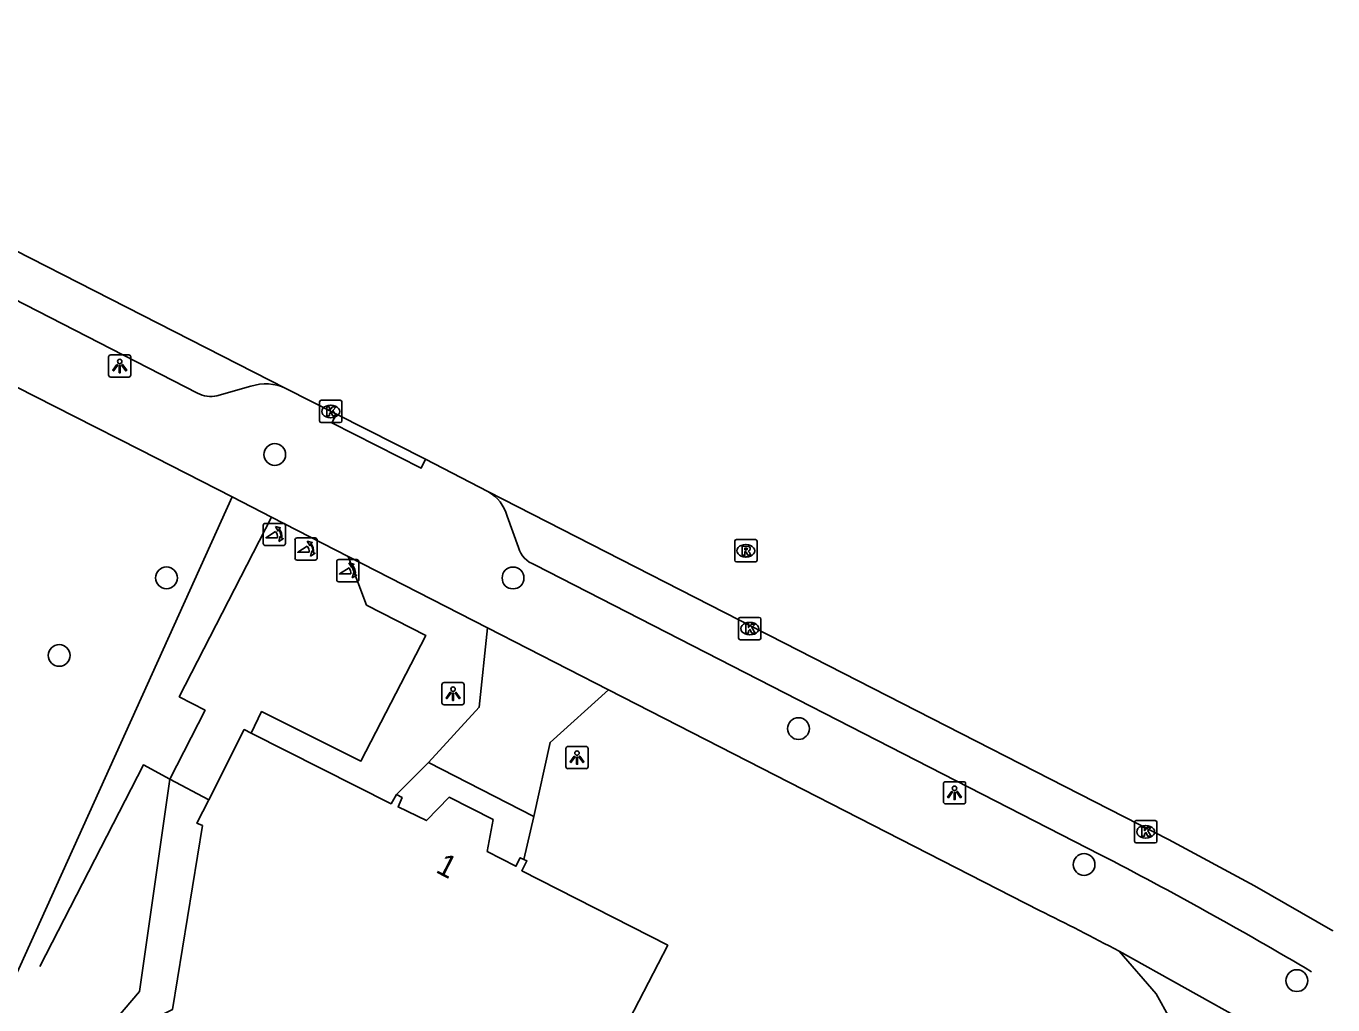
# Model space of a CAD drawing. Extents: x 159503 to 160347, y 382525 to 383272.
# Drawn here: x 160288.6 to 160347.2, y 382897.3 to 382941.2 of the extents above; entities that cross this region are included whole.
import ezdxf

# ---------------------------------------------------------------- set-up
doc = ezdxf.new("R2010")
doc.units = 0
for name, color, linetype in [('IMGEO_Boom', 7, 'Continuous'), ('IMGEO_Groenvoorziening', 7, 'Continuous'), ('IMGEO_Hek', 7, 'Continuous'), ('IMGEO_Kolk', 7, 'Continuous'), ('IMGEO_Lichtpunt', 7, 'Continuous'), ('IMGEO_Loofbos', 7, 'Continuous'), ('IMGEO_Pand', 7, 'Continuous'), ('IMGEO_Pand_nummerreeks', 7, 'Continuous'), ('IMGEO_Parkeervlak_open', 7, 'Continuous'), ('IMGEO_Poller', 7, 'Continuous'), ('IMGEO_Rijbaan_lokaal_open', 7, 'Continuous'), ('IMGEO_Rioolput', 7, 'Continuous'), ('IMGEO_Voetpad_open', 7, 'Continuous')]:
    doc.layers.add(name, color=color, linetype=linetype)

msp = doc.modelspace()

# ---------------------------------------------------------------- linework, layer by layer
at = {"layer": 'IMGEO_Boom'}
for centre in [(160299.715, 382921.985), (160294.859, 382916.452), (160310.401, 382916.448), (160290.047, 382912.974), (160323.206, 382909.691), (160336.012, 382903.594), (160345.555, 382898.387)]:
    msp.add_circle(centre, 0.489, dxfattribs=at)
at = {"layer": 'IMGEO_Groenvoorziening'}
msp.add_lwpolyline([(160337.58, 382899.708), (160339.246, 382897.788), (160339.864, 382896.69), (160340.213, 382895.657), (160340.37, 382894.676), (160340.378, 382893.79), (160340.246, 382892.846), (160340.012, 382892.038), (160339.449, 382890.88), (160338.678, 382889.878), (160313.605, 382875.081)], dxfattribs=at)
at = {"layer": 'IMGEO_Hek'}
for points in [[(160289.183, 382899.021), (160293.821, 382908.06), (160295.01, 382907.43)], [(160295.01, 382907.43), (160296.757, 382906.504)]]:
    msp.add_lwpolyline(points, dxfattribs=at)
at = {"layer": 'IMGEO_Kolk'}
for p, q in [((160301.725, 382923.492), (160301.725, 382924.344)), ((160301.8, 382924.418), (160302.652, 382924.418)), ((160302.213, 382924.198), (160302.238, 382924.198)), ((160302.726, 382924.344), (160302.726, 382923.492)), ((160302.652, 382923.418), (160301.8, 382923.418)), ((160302.236, 382923.638), (160302.211, 382923.638)), ((160320.593, 382914.677), (160321.445, 382914.677)), ((160320.518, 382913.751), (160320.518, 382914.603)), ((160321.006, 382914.457), (160321.031, 382914.457)), ((160321.519, 382914.603), (160321.519, 382913.751)), ((160321.445, 382913.677), (160320.593, 382913.677)), ((160321.029, 382913.897), (160321.004, 382913.897)), ((160338.275, 382904.638), (160338.275, 382905.49)), ((160338.35, 382905.564), (160339.202, 382905.564)), ((160338.763, 382905.344), (160338.788, 382905.344)), ((160339.276, 382905.49), (160339.276, 382904.638)), ((160338.786, 382904.784), (160338.761, 382904.784)), ((160339.202, 382904.564), (160338.35, 382904.564))]:
    msp.add_line(p, q, dxfattribs=at)
for points in [[(160301.725, 382923.492), (160301.725, 382924.344)], [(160301.8, 382924.418), (160302.652, 382924.418)], [(160302.046, 382924.118), (160302.169, 382924.118), (160302.169, 382923.967), (160302.299, 382924.118), (160302.463, 382924.118), (160302.317, 382923.967), (160302.47, 382923.718), (160302.318, 382923.718), (160302.233, 382923.882), (160302.169, 382923.815), (160302.169, 382923.718), (160302.046, 382923.718), (160302.046, 382924.118)], [(160302.726, 382924.344), (160302.726, 382923.492)], [(160302.652, 382923.418), (160301.8, 382923.418)], [(160320.593, 382914.677), (160321.445, 382914.677)], [(160320.518, 382913.751), (160320.518, 382914.603)], [(160320.839, 382914.377), (160320.962, 382914.377), (160320.962, 382914.226), (160321.092, 382914.377), (160321.256, 382914.377), (160321.11, 382914.226), (160321.263, 382913.977), (160321.111, 382913.977), (160321.026, 382914.141), (160320.962, 382914.074), (160320.962, 382913.977), (160320.839, 382913.977), (160320.839, 382914.377)], [(160321.519, 382914.603), (160321.519, 382913.751)], [(160321.445, 382913.677), (160320.593, 382913.677)], [(160338.275, 382904.638), (160338.275, 382905.49)], [(160338.35, 382905.564), (160339.202, 382905.564)], [(160338.596, 382905.264), (160338.719, 382905.264), (160338.719, 382905.113), (160338.849, 382905.264), (160339.013, 382905.264), (160338.867, 382905.113), (160339.02, 382904.864), (160338.868, 382904.864), (160338.783, 382905.028), (160338.719, 382904.961), (160338.719, 382904.864), (160338.596, 382904.864), (160338.596, 382905.264)], [(160339.276, 382905.49), (160339.276, 382904.638)], [(160339.202, 382904.564), (160338.35, 382904.564)]]:
    msp.add_lwpolyline(points, dxfattribs=at)
for centre, start, end in [((160301.802, 382924.342), 91.55205, 178.44795), ((160301.802, 382924.342), 91.55205, 178.44795), ((160302.65, 382924.342), 1.55205, 88.44795), ((160302.65, 382924.342), 1.55205, 88.44795), ((160301.802, 382923.494), 181.55205, 268.44795), ((160301.802, 382923.494), 181.55205, 268.44795), ((160302.65, 382923.494), 271.55205, 358.44795), ((160302.65, 382923.494), 271.55205, 358.44795), ((160320.595, 382914.601), 91.55205, 178.44795), ((160320.595, 382914.601), 91.55205, 178.44795), ((160321.443, 382914.601), 1.55205, 88.44795), ((160321.443, 382914.601), 1.55205, 88.44795), ((160320.595, 382913.753), 181.55205, 268.44795), ((160320.595, 382913.753), 181.55205, 268.44795), ((160321.443, 382913.753), 271.55205, 358.44795), ((160321.443, 382913.753), 271.55205, 358.44795), ((160338.352, 382905.488), 91.55205, 178.44795), ((160338.352, 382905.488), 91.55205, 178.44795), ((160339.2, 382905.488), 1.55205, 88.44795), ((160339.2, 382905.488), 1.55205, 88.44795), ((160338.352, 382904.64), 181.55205, 268.44795), ((160338.352, 382904.64), 181.55205, 268.44795), ((160339.2, 382904.64), 271.55205, 358.44795), ((160339.2, 382904.64), 271.55205, 358.44795)]:
    msp.add_arc(centre, 0.0765, start, end, dxfattribs=at)
for centre, major_axis, ratio, start_param, end_param in [((160302.212, 382923.918), (-0.387, 0.002), 0.722429, 4.712389, 7.853982), ((160302.237, 382923.918), (-0.39, 0.002), 0.717154, 1.570796, 4.712389), ((160321.005, 382914.177), (-0.387, 0.002), 0.722429, 4.712389, 7.853982), ((160321.03, 382914.177), (-0.39, 0.002), 0.717154, 1.570796, 4.712389), ((160338.762, 382905.064), (-0.387, 0.002), 0.722429, 4.712389, 7.853982), ((160338.787, 382905.064), (-0.39, 0.002), 0.717154, 1.570796, 4.712389)]:
    msp.add_ellipse(centre, major_axis=major_axis, ratio=ratio, start_param=start_param, end_param=end_param, dxfattribs=at)
at = {"layer": 'IMGEO_Lichtpunt'}
for p, q in [((160292.262, 382926.362), (160292.262, 382925.555)), ((160292.262, 382926.362), (160292.262, 382925.555)), ((160293.164, 382926.457), (160292.356, 382926.457)), ((160293.164, 382926.457), (160292.356, 382926.457)), ((160293.258, 382925.555), (160293.258, 382926.362)), ((160293.258, 382925.555), (160293.258, 382926.362)), ((160292.356, 382925.461), (160293.164, 382925.461)), ((160292.356, 382925.461), (160293.164, 382925.461)), ((160308.115, 382911.757), (160307.307, 382911.757)), ((160308.115, 382911.757), (160307.307, 382911.757)), ((160307.213, 382911.662), (160307.213, 382910.855)), ((160307.213, 382911.662), (160307.213, 382910.855)), ((160308.209, 382910.855), (160308.209, 382911.662)), ((160308.209, 382910.855), (160308.209, 382911.662)), ((160307.307, 382910.761), (160308.115, 382910.761)), ((160307.307, 382910.761), (160308.115, 382910.761)), ((160312.772, 382908.796), (160312.772, 382907.989)), ((160312.772, 382908.796), (160312.772, 382907.989)), ((160313.674, 382908.891), (160312.866, 382908.891)), ((160313.674, 382908.891), (160312.866, 382908.891)), ((160313.768, 382907.989), (160313.768, 382908.796)), ((160313.768, 382907.989), (160313.768, 382908.796)), ((160312.866, 382907.895), (160313.674, 382907.895)), ((160312.866, 382907.895), (160313.674, 382907.895)), ((160329.703, 382907.216), (160329.703, 382906.409)), ((160329.703, 382907.216), (160329.703, 382906.409)), ((160330.605, 382907.311), (160329.797, 382907.311)), ((160330.605, 382907.311), (160329.797, 382907.311)), ((160330.699, 382906.409), (160330.699, 382907.216)), ((160330.699, 382906.409), (160330.699, 382907.216)), ((160329.797, 382906.315), (160330.605, 382906.315)), ((160329.797, 382906.315), (160330.605, 382906.315))]:
    msp.add_line(p, q, dxfattribs=at)
for points in [[(160292.636, 382926.026), (160292.675, 382925.998), (160292.487, 382925.736), (160292.449, 382925.763), (160292.636, 382926.026)], [(160292.738, 382925.978), (160292.785, 382925.978), (160292.785, 382925.656), (160292.738, 382925.656), (160292.738, 382925.978)], [(160292.848, 382925.998), (160292.886, 382926.025), (160293.073, 382925.763), (160293.034, 382925.735), (160292.848, 382925.998)], [(160307.587, 382911.326), (160307.626, 382911.298), (160307.438, 382911.036), (160307.4, 382911.063), (160307.587, 382911.326)], [(160307.689, 382911.278), (160307.736, 382911.278), (160307.736, 382910.956), (160307.689, 382910.956), (160307.689, 382911.278)], [(160307.799, 382911.298), (160307.837, 382911.325), (160308.024, 382911.063), (160307.985, 382911.035), (160307.799, 382911.298)], [(160313.146, 382908.46), (160313.185, 382908.432), (160312.997, 382908.17), (160312.959, 382908.197), (160313.146, 382908.46)], [(160313.248, 382908.412), (160313.295, 382908.412), (160313.295, 382908.09), (160313.248, 382908.09), (160313.248, 382908.412)], [(160313.358, 382908.432), (160313.396, 382908.459), (160313.583, 382908.197), (160313.544, 382908.169), (160313.358, 382908.432)], [(160330.077, 382906.88), (160330.116, 382906.852), (160329.928, 382906.59), (160329.89, 382906.617), (160330.077, 382906.88)], [(160330.179, 382906.832), (160330.226, 382906.832), (160330.226, 382906.51), (160330.179, 382906.51), (160330.179, 382906.832)], [(160330.289, 382906.852), (160330.327, 382906.879), (160330.514, 382906.617), (160330.475, 382906.589), (160330.289, 382906.852)]]:
    msp.add_lwpolyline(points, dxfattribs=at)
for centre in [(160292.761, 382926.16), (160307.712, 382911.46), (160313.271, 382908.594), (160330.202, 382907.014)]:
    msp.add_circle(centre, 0.0994, dxfattribs=at)
for centre, start, end in [((160292.356, 382926.362), 90, 180), ((160292.356, 382926.362), 90, 180), ((160293.164, 382926.362), 0, 90), ((160293.164, 382926.362), 0, 90), ((160292.356, 382925.555), 180, 270), ((160292.356, 382925.555), 180, 270), ((160293.164, 382925.555), 270, 0), ((160293.164, 382925.555), 270, 360), ((160307.307, 382911.662), 90, 180), ((160307.307, 382911.662), 90, 180), ((160308.115, 382911.662), 0, 90), ((160308.115, 382911.662), 0, 90), ((160307.307, 382910.855), 180, 270), ((160307.307, 382910.855), 180, 270), ((160308.115, 382910.855), 270, 0), ((160308.115, 382910.855), 270, 360), ((160312.866, 382908.796), 90, 180), ((160312.866, 382908.796), 90, 180), ((160313.674, 382908.796), 0, 90), ((160313.674, 382908.796), 0, 90), ((160312.866, 382907.989), 180, 270), ((160312.866, 382907.989), 180, 270), ((160313.674, 382907.989), 270, 0), ((160313.674, 382907.989), 270, 360), ((160329.797, 382907.216), 90, 180), ((160329.797, 382907.216), 90, 180), ((160330.605, 382907.216), 0, 90), ((160330.605, 382907.216), 0, 90), ((160329.797, 382906.409), 180, 270), ((160329.797, 382906.409), 180, 270), ((160330.605, 382906.409), 270, 0), ((160330.605, 382906.409), 270, 360)]:
    msp.add_arc(centre, 0.0946, start, end, dxfattribs=at)
at = {"layer": 'IMGEO_Loofbos'}
msp.add_lwpolyline([(160297.798, 382920.081), (160281.12, 382883.208)], dxfattribs=at)
at = {"layer": 'IMGEO_Pand'}
for points in [[(160296.757, 382906.504), (160298.346, 382909.65), (160298.653, 382909.494)], [(160305.168, 382906.741), (160304.929, 382906.318), (160298.653, 382909.494)], [(160296.757, 382906.504), (160296.224, 382905.449), (160296.47, 382905.339), (160295.13, 382897.097), (160294.615, 382896.84), (160292.189, 382894.395), (160290.933, 382888.185)], [(160305.168, 382906.741), (160305.426, 382906.598), (160305.244, 382906.18), (160306.516, 382905.568), (160307.54, 382906.616), (160309.508, 382905.61), (160309.243, 382904.181), (160310.534, 382903.517), (160310.728, 382903.898), (160310.892, 382903.819)], [(160310.892, 382903.819), (160311.025, 382903.755), (160310.795, 382903.318), (160317.343, 382899.976), (160315.181, 382895.795), (160314.983, 382895.908), (160308.995, 382890.048), (160309.03, 382889.941), (160309.117, 382889.708), (160309.132, 382889.471), (160308.622, 382886.049), (160308.57, 382885.927), (160308.415, 382885.684), (160307.904, 382885.173)]]:
    msp.add_lwpolyline(points, dxfattribs=at)
at = {"layer": 'IMGEO_Parkeervlak_open'}
for points in [[(160295.01, 382907.43), (160296.593, 382910.516), (160295.433, 382911.12), (160299.564, 382919.177)], [(160298.653, 382909.494), (160299.127, 382910.458), (160303.576, 382908.234), (160306.497, 382913.866), (160303.833, 382915.235), (160303.004, 382917.415)]]:
    msp.add_lwpolyline(points, dxfattribs=at)
at = {"layer": 'IMGEO_Poller'}
for p, q in [((160299.199, 382918.803), (160299.199, 382917.996)), ((160299.199, 382918.803), (160299.199, 382917.996)), ((160300.101, 382918.898), (160299.293, 382918.898)), ((160300.101, 382918.898), (160299.293, 382918.898)), ((160300.195, 382917.996), (160300.195, 382918.803)), ((160300.195, 382917.996), (160300.195, 382918.803)), ((160300.623, 382918.15), (160300.623, 382917.343)), ((160300.623, 382918.15), (160300.623, 382917.343)), ((160301.525, 382918.245), (160300.717, 382918.245)), ((160301.525, 382918.245), (160300.717, 382918.245)), ((160301.619, 382917.343), (160301.619, 382918.15)), ((160301.619, 382917.343), (160301.619, 382918.15)), ((160299.293, 382917.901), (160300.101, 382917.901)), ((160299.293, 382917.901), (160300.101, 382917.901)), ((160300.717, 382917.248), (160301.525, 382917.248)), ((160300.717, 382917.248), (160301.525, 382917.248)), ((160302.493, 382917.177), (160302.493, 382916.37)), ((160302.493, 382917.177), (160302.493, 382916.37)), ((160303.395, 382917.272), (160302.587, 382917.272)), ((160303.395, 382917.272), (160302.587, 382917.272)), ((160303.489, 382916.37), (160303.489, 382917.177)), ((160303.489, 382916.37), (160303.489, 382917.177)), ((160302.587, 382916.275), (160303.395, 382916.275)), ((160302.587, 382916.275), (160303.395, 382916.275))]:
    msp.add_line(p, q, dxfattribs=at)
for points in [[(160299.878, 382918.627), (160299.866, 382918.554), (160299.741, 382918.759)], [(160299.741, 382918.759), (160299.972, 382918.693), (160299.901, 382918.661)], [(160299.834, 382918.254), (160299.321, 382918.254), (160299.751, 382918.529)], [(160299.894, 382918.082), (160299.96, 382918.313), (160299.99, 382918.245)], [(160300.026, 382918.218), (160300.098, 382918.207), (160299.894, 382918.082)], [(160301.258, 382917.601), (160300.745, 382917.601), (160301.175, 382917.876)], [(160301.302, 382917.974), (160301.29, 382917.901), (160301.165, 382918.106)], [(160301.165, 382918.106), (160301.396, 382918.04), (160301.325, 382918.008)], [(160301.318, 382917.429), (160301.384, 382917.66), (160301.414, 382917.592)], [(160301.45, 382917.565), (160301.522, 382917.554), (160301.318, 382917.429)], [(160303.172, 382917.001), (160303.16, 382916.928), (160303.035, 382917.133)], [(160303.035, 382917.133), (160303.266, 382917.067), (160303.195, 382917.035)], [(160303.128, 382916.628), (160302.615, 382916.628), (160303.045, 382916.903)], [(160303.188, 382916.456), (160303.254, 382916.687), (160303.284, 382916.619)], [(160303.32, 382916.592), (160303.392, 382916.581), (160303.188, 382916.456)]]:
    msp.add_lwpolyline(points, dxfattribs=at)
for centre, radius, start, end in [((160299.293, 382918.803), 0.0946, 90, 180), ((160299.293, 382918.803), 0.0946, 90, 180), ((160300.101, 382918.803), 0.0946, 0, 90), ((160300.101, 382918.803), 0.0946, 0, 90), ((160299.506, 382918.304), 0.332, 351.32473, 42.4854), ((160299.52, 382918.314), 0.476, 351.75274, 41.16905), ((160299.52, 382918.314), 0.516, 349.35686, 42.29123), ((160300.717, 382918.15), 0.0946, 90, 180), ((160300.717, 382918.15), 0.0946, 90, 180), ((160301.525, 382918.15), 0.0946, 0, 90), ((160301.525, 382918.15), 0.0946, 0, 90), ((160299.293, 382917.996), 0.0946, 180, 270), ((160299.293, 382917.996), 0.0946, 180, 270), ((160300.101, 382917.996), 0.0946, 270, 0), ((160300.101, 382917.996), 0.0946, 270, 0), ((160300.93, 382917.651), 0.332, 351.32473, 42.4854), ((160300.944, 382917.661), 0.476, 351.75274, 41.16905), ((160300.944, 382917.661), 0.516, 349.35686, 42.29123), ((160300.717, 382917.343), 0.0946, 180, 270), ((160300.717, 382917.343), 0.0946, 180, 270), ((160301.525, 382917.343), 0.0946, 270, 0), ((160301.525, 382917.343), 0.0946, 270, 0), ((160302.587, 382917.177), 0.0946, 90, 180), ((160302.587, 382917.177), 0.0946, 90, 180), ((160302.814, 382916.688), 0.476, 351.75274, 41.16905), ((160302.814, 382916.688), 0.516, 349.35686, 42.29123), ((160303.395, 382917.177), 0.0946, 0, 90), ((160303.395, 382917.177), 0.0946, 0, 90), ((160302.8, 382916.678), 0.332, 351.32473, 42.4854), ((160302.587, 382916.37), 0.0946, 180, 270), ((160302.587, 382916.37), 0.0946, 180, 270), ((160303.395, 382916.37), 0.0946, 270, 0), ((160303.395, 382916.37), 0.0946, 270, 0)]:
    msp.add_arc(centre, radius, start, end, dxfattribs=at)
at = {"layer": 'IMGEO_Rijbaan_lokaal_open'}
for points in [[(160279.467, 382935.529), (160300.207, 382924.953)], [(160302.485, 382923.802), (160300.207, 382924.953)], [(160302.485, 382923.802), (160306.48, 382921.77)], [(160309.276, 382920.322), (160306.48, 382921.77)], [(160347.17, 382900.617), (160347.17, 382900.617), (160343.654, 382902.641), (160339.795, 382904.723), (160309.276, 382920.322)]]:
    msp.add_lwpolyline(points, dxfattribs=at)
at = {"layer": 'IMGEO_Rioolput'}
for p, q in [((160320.418, 382918.169), (160321.27, 382918.169)), ((160320.343, 382917.243), (160320.343, 382918.095)), ((160320.831, 382917.949), (160320.856, 382917.949)), ((160321.344, 382918.095), (160321.344, 382917.243)), ((160321.27, 382917.169), (160320.418, 382917.169)), ((160320.854, 382917.389), (160320.829, 382917.389))]:
    msp.add_line(p, q, dxfattribs=at)
for points in [[(160320.418, 382918.169), (160321.27, 382918.169)], [(160320.343, 382917.243), (160320.343, 382918.095)], [(160320.932, 382917.867), (160320.68, 382917.869), (160320.68, 382917.469)], [(160320.68, 382917.469), (160320.804, 382917.469), (160320.804, 382917.631), (160320.815, 382917.631)], [(160320.858, 382917.788), (160320.804, 382917.788), (160320.804, 382917.707)], [(160320.804, 382917.707), (160320.856, 382917.707)], [(160320.862, 382917.602), (160320.933, 382917.469), (160321.073, 382917.469), (160321.008, 382917.595)], [(160321.344, 382918.095), (160321.344, 382917.243)], [(160321.27, 382917.169), (160320.418, 382917.169)]]:
    msp.add_lwpolyline(points, dxfattribs=at)
for centre, radius, start, end in [((160320.42, 382918.093), 0.0765, 91.55205, 178.44795), ((160320.42, 382918.093), 0.0765, 91.55205, 178.44795), ((160321.268, 382918.093), 0.0765, 1.55205, 88.44795), ((160321.268, 382918.093), 0.0765, 1.55205, 88.44795), ((160320.814, 382917.578), 0.0533, 26.02933, 88.69889), ((160320.84, 382917.896), 0.19, 274.7715, 282.96867), ((160320.864, 382917.692), 0.0964, 77.00612, 93.18647), ((160320.878, 382917.749), 0.0378, 276.66336, 79.67722), ((160320.931, 382917.757), 0.109, 350.36119, 89.41601), ((160320.929, 382917.757), 0.112, 277.58423, 350.98172), ((160320.913, 382917.542), 0.108, 29.51342, 73.79051), ((160320.42, 382917.245), 0.0765, 181.55205, 268.44795), ((160320.42, 382917.245), 0.0765, 181.55205, 268.44795), ((160321.268, 382917.245), 0.0765, 271.55205, 358.44795), ((160321.268, 382917.245), 0.0765, 271.55205, 358.44795)]:
    msp.add_arc(centre, radius, start, end, dxfattribs=at)
for centre, major_axis, ratio, start_param, end_param in [((160320.83, 382917.669), (-0.387, 0.002), 0.722429, 4.712389, 7.853982), ((160320.855, 382917.669), (-0.39, 0.002), 0.717154, 1.570796, 4.712389)]:
    msp.add_ellipse(centre, major_axis=major_axis, ratio=ratio, start_param=start_param, end_param=end_param, dxfattribs=at)
at = {"layer": 'IMGEO_Voetpad_open'}
for points in [[(160256.305, 382941.201), (160267.269, 382935.624), (160290.738, 382923.687), (160293.682, 382922.189), (160297.798, 382920.081)], [(160296.253, 382924.736), (160278.588, 382933.799)], [(160298.643, 382925.046), (160297.124, 382924.622)], [(160306.48, 382921.77), (160306.274, 382921.37), (160302.268, 382923.408), (160302.485, 382923.802)], [(160297.798, 382920.081), (160299.564, 382919.177)], [(160299.564, 382919.177), (160303.004, 382917.415)], [(160310.142, 382919.223), (160310.641, 382917.818)], [(160303.004, 382917.415), (160309.263, 382914.21)], [(160311.385, 382917.044), (160336.75, 382904.037)], [(160309.263, 382914.21), (160308.889, 382910.65), (160306.616, 382908.178)], [(160309.263, 382914.21), (160314.69, 382911.431)], [(160314.69, 382911.431), (160312.062, 382909.07), (160311.33, 382905.751)], [(160314.69, 382911.431), (160334.009, 382901.537)], [(160306.616, 382908.178), (160305.168, 382906.741)], [(160311.33, 382905.751), (160306.616, 382908.178)], [(160302.807, 382880.492), (160303.398, 382879.562), (160299.29, 382878.733), (160291.637, 382882.353), (160289.455, 382886.708), (160290.802, 382894.566), (160293.646, 382897.904), (160295.01, 382907.43)], [(160295.01, 382907.43), (160296.757, 382906.504)], [(160311.33, 382905.751), (160310.892, 382903.819)], [(160337.58, 382899.708), (160343.472, 382896.422), (160344.077, 382896.065)]]:
    msp.add_lwpolyline(points, dxfattribs=at)
for centre, radius, start, end in [((160296.84, 382925.84), 1.25, 241.97465, 283.11192), ((160299.313, 382923.111), 2.048, 64.10606, 109.088), ((160308.368, 382918.716), 1.845, 15.96032, 60.51512), ((160311.721, 382918.111), 1.119, 195.19176, 252.54388), ((160252.702, 382741.444), 183.032, 59.27396, 62.6645), ((160263.814, 382760.085), 157.912, 62.15143, 63.60721)]:
    msp.add_arc(centre, radius, start, end, dxfattribs=at)

# ---------------------------------------------------------------- texts
at = {"layer": 'IMGEO_Pand_nummerreeks'}
msp.add_text('1', height=1, rotation=332.92484, dxfattribs=at).set_placement((160306.888, 382903.266))

doc.saveas('drawing.dxf')
